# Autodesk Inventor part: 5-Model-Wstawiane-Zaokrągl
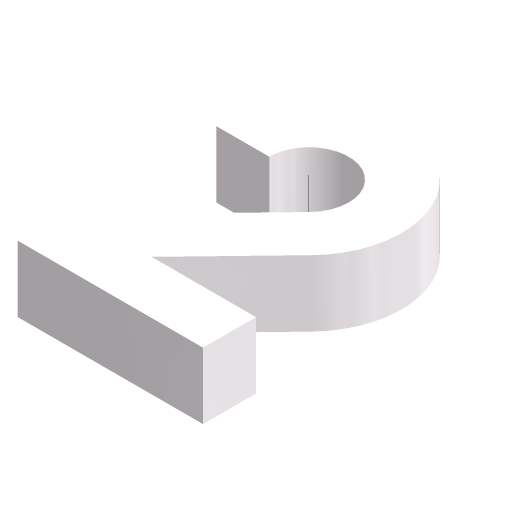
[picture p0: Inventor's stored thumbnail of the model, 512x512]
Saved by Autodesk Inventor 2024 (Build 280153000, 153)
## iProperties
Company: ATC
Shininess: 21.0
Length Units: 11269
Angle Units: 11279
Time Units: 11290
Mass Units: 11283
Length Display Precision: 3
Angle Display Precision: 2
Compacted: True
Created: 2023-03
Part Number: 5-Model-Wstawiane-Zaokrągl
Document SubType Name: Modeling
Designer: Andrzej Jaskulski
Material: Kurs-AJ
Density: 1 g/cm^3
Appearance: Kurs-AJ
Checked By: A.J.
Engr Approved By: Andrzej Jaskulski
Mfg Approved By: Andrzej Jaskulski
Authority: A.J.
Density: 0.0
Volumn: 0.0
Area: 0.0
PropertySet Name: Model Information
Control State: 0
Master: False
Checked Out: False
Title: A.J.: Kurs R2024-MEP
Author: Andrzej Jaskulski
Revision Number: 1/24
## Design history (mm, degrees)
sketch "Zarys dwójki"
  geometry: L1 (140, 0.063)-(0, 0.063) reference; L2 (0, 0.063)-(0, 34.389) reference; L3 (0, 150.063)-(40, 150.063); L4 (140, 0.063)-(140, 40.063); L5 (140, 40.063)-(61.086, 40.063); L6 (61.086, 40.063)-(120.354, 101.437); L7 (91.58, 129.223)-(0, 34.389); A1 r 30 centre (70, 150.063) between (91.58, 129.223) and (40, 150.063); A2 r 70 centre (70, 150.063) between (120.354, 101.437) and (0, 150.063)
  constraints: 14 end point, 4 perpendicular, 4 point on circle, 2 centre point, 2 parallel, 2 tangent, 1 coincident
  dimensions: "d0" = 140 distance of L1.start L1.end; "d1" = 150 vertical distance of A1.centre L1.end; "d2" = 70 horizontal distance of L1.end A1.centre; "d3" = 46 deg angle of L6 L5; "d4" = 150 distance of L3.start L1.end (= d1); "d5" = 30 radius of A1; "d6" = 70 radius of A2
extrude "Dwójka" new body sketch "Zarys dwójki" distance "d7" = 50; taper "d8" = 0 deg
node "Oś walca"
node "Bryła1"
node "Korpusy bryłowe"
node "Korpusy powierzchniowe"
other parameters: "d9" = 90 deg
